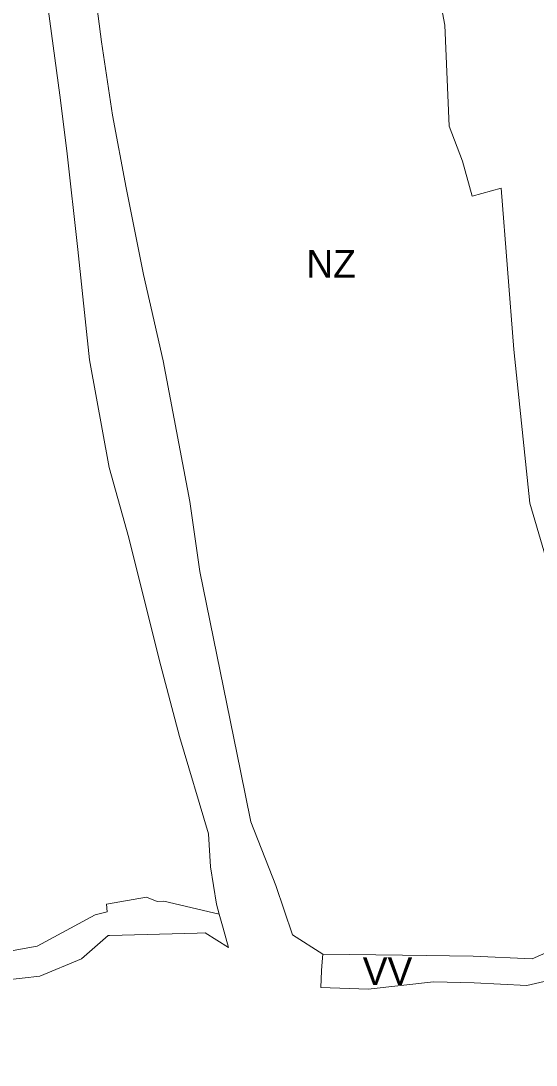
# Model space of a CAD drawing. Extents: x -650451 to -642268, y -1075216 to -1066610.
# Drawn here: x -645357.2 to -645134.8, y -1073326.2 to -1072876 of the extents above; entities that cross this region are included whole.
import ezdxf

# ---------------------------------------------------------------- set-up
doc = ezdxf.new("R2010")
doc.units = 0
doc.header["$LTSCALE"] = 4.8
doc.layers.add('45', color=7, linetype='Continuous', lineweight=13)
doc.layers.add('46', color=7, linetype='Continuous', lineweight=13)
doc.layers.add('62', color=7, linetype='Continuous')

msp = doc.modelspace()

# ---------------------------------------------------------------- linework, layer by layer
at = {"layer": '45'}
for points in [[(-645226.847, -1073278.345), (-645192.45, -1073278.84), (-645161.91, -1073279.24), (-645136.55, -1073280.36), (-645096.96, -1073263.01), (-645090.9, -1073260.31), (-645081.07, -1073256.01), (-645043.97, -1073244.09), (-645043.68, -1073245.61), (-645044.246, -1073224.619)], [(-645499.41, -1073318.24), (-645476.1, -1073316.93), (-645457.38, -1073313.78), (-645427.83, -1073301.03), (-645404.03, -1073288.01), (-645389.08, -1073281.94), (-645350.08, -1073274.88), (-645325.07, -1073261.39), (-645319.96, -1073260.12), (-645320.244, -1073256.876), (-645302.963, -1073253.878), (-645298.27, -1073255.65), (-645295.44, -1073255.48), (-645271.52, -1073261.16)], [(-645271.52, -1073261.16), (-645269.83, -1073267.22), (-645267.53, -1073275.44)], [(-645267.53, -1073275.44), (-645277.57, -1073269.17), (-645281.1, -1073269.26), (-645318.94, -1073270.27), (-645319.42, -1073270.28), (-645331.05, -1073280.34), (-645348.9, -1073287.85), (-645364.15, -1073289.58), (-645381.21, -1073286.79), (-645414.6, -1073312.83), (-645431.37, -1073313.2), (-645442.26, -1073319.33), (-645459.78, -1073326.21), (-645492.16, -1073323.95), (-645492.7, -1073323.51), (-645499.41, -1073318.24)], [(-645227.744, -1073292.736), (-645227.35, -1073285.55), (-645227.199, -1073283.366), (-645226.847, -1073278.345)], [(-645109.6, -1073280.56), (-645119.56, -1073287.5), (-645138.82, -1073291.94), (-645161.51, -1073290.8), (-645179.11, -1073290.25), (-645207.27, -1073293.52), (-645227.744, -1073292.736)]]:
    msp.add_lwpolyline(points, dxfattribs=at)
at = {"layer": '46'}
for points in [[(-645213.34, -1072669.98), (-645174.13, -1072877.93), (-645172.28, -1072921.42), (-645166.48, -1072936.5), (-645162.379, -1072951.55), (-645149.84, -1072948.13), (-645144.37, -1073017.64), (-645137.5, -1073083.97), (-645119.34, -1073145.61)], [(-645226.847, -1073278.345), (-645239.9, -1073270.025), (-645247.051, -1073248.736), (-645257.842, -1073221.36), (-645262.388, -1073199.409), (-645279.878, -1073113.356), (-645284.269, -1073083.286), (-645295.788, -1073022.556), (-645304.24, -1072985.372), (-645311.772, -1072947.945), (-645317.65, -1072916.642), (-645322.284, -1072885.085), (-645327.091, -1072848.387), (-645333.718, -1072799.987), (-645338.023, -1072755.969), (-645338.538, -1072746.821)], [(-645353.86, -1072794.339), (-645350.822, -1072830.388), (-645340.345, -1072908.029), (-645337.34, -1072932.073), (-645332.517, -1072974.538), (-645327.554, -1073022.214)], [(-645327.554, -1073022.214), (-645319.052, -1073068.6), (-645310.558, -1073098.946), (-645297.395, -1073151.294)], [(-645297.395, -1073151.294), (-645288.647, -1073184.518), (-645276.125, -1073226.571), (-645275.269, -1073240.71), (-645272.747, -1073256.762), (-645271.52, -1073261.16)], [(-645044.246, -1073224.619), (-645043.68, -1073245.61), (-645043.97, -1073244.09), (-645081.07, -1073256.01), (-645090.9, -1073260.31), (-645096.96, -1073263.01), (-645136.55, -1073280.36), (-645161.91, -1073279.24), (-645192.45, -1073278.84), (-645226.847, -1073278.345)], [(-645271.52, -1073261.16), (-645295.44, -1073255.48), (-645298.27, -1073255.65), (-645302.963, -1073253.878), (-645320.244, -1073256.876), (-645319.96, -1073260.12), (-645325.07, -1073261.39), (-645350.08, -1073274.88), (-645389.08, -1073281.94), (-645404.03, -1073288.01), (-645427.83, -1073301.03), (-645457.38, -1073313.78), (-645476.1, -1073316.93), (-645499.41, -1073318.24)]]:
    msp.add_lwpolyline(points, dxfattribs=at)

# ---------------------------------------------------------------- texts
at = {"layer": '62'}
for s, p in [('NZ', (-645233.947, -1072986.747)), ('VV', (-645209.607, -1073291.741))]:
    msp.add_text(s, height=12, dxfattribs=at).set_placement(p)

doc.saveas('drawing.dxf')
